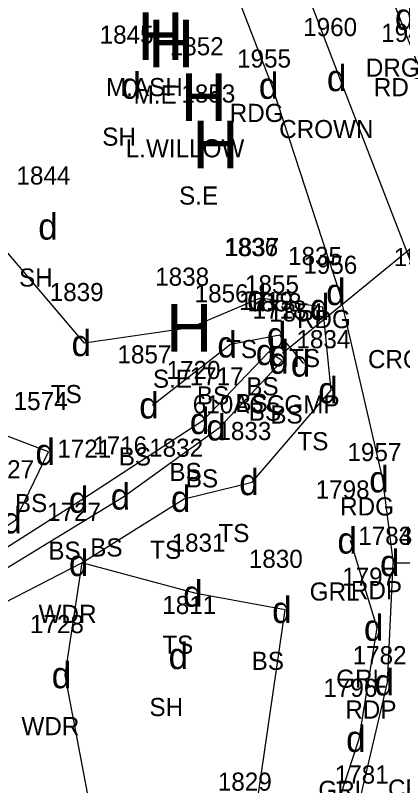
# Model space of a CAD drawing. Extents: x 461160 to 461373, y 202903 to 203086.
# Drawn here: x 461314.15 to 461330.39, y 202994.66 to 203026.97 of the extents above; entities that cross this region are included whole.
import ezdxf

# ---------------------------------------------------------------- set-up
doc = ezdxf.new("R2010")
doc.units = 0
for name, color, linetype in [('Level 11', 7, 'Continuous'), ('Level 12', 7, 'Continuous'), ('Level 14', 7, 'Continuous'), ('Level 46', 7, 'Continuous'), ('Level 47', 7, 'Continuous'), ('Level 48', 7, 'Continuous'), ('Level 49', 7, 'Continuous'), ('Level 59', 7, 'Continuous')]:
    doc.layers.add(name, color=color, linetype=linetype)

msp = doc.modelspace()

# ---------------------------------------------------------------- linework, layer by layer
at = {"layer": 'Level 11'}
for points in [[(461337.431, 203004.112), (461335.803, 203008.917), (461333.619, 203019.078), (461330.951, 203025.095), (461326.97, 203035.309), (461323.195, 203044.309), (461319.052, 203055.572), (461315.04, 203065.78), (461311.172, 203077.068)], [(461305.411, 203075.794), (461308.179, 203066.87), (461311.606, 203057.835), (461315.035, 203048.923), (461318.285, 203040.867), (461321.673, 203032.386), (461324.91, 203024.016), (461327.727, 203015.366), (461329.538, 203007.508), (461329.989, 203003.994)], [(461368.16, 202993.988), (461361.614, 202999.669), (461352.956, 203006.007), (461341.424, 203009.197), (461337.518, 203007.355), (461337.431, 203004.112), (461337.186, 202997.424), (461334.068, 202989.63), (461330.234, 202984.513), (461326.916, 202981.421), (461323.296, 202985.661), (461325.835, 202988.474), (461328.575, 202993.98), (461329.756, 202998.988), (461329.989, 203003.994), (461337.431, 203004.112), (461329.989, 203003.994)]]:
    msp.add_lwpolyline(points, dxfattribs=at)
at = {"layer": 'Level 12'}
msp.add_lwpolyline([(461323.672, 202986.332), (461326.722, 202990.981), (461328.569, 202996.619), (461329.316, 203001.28), (461328.204, 203004.939)], dxfattribs=at)
at = {"layer": 'Level 14'}
msp.add_lwpolyline([(461301.65, 202990.994), (461304.551, 202996.947), (461311.823, 203001.37), (461316.945, 203004), (461316.225, 202999.291), (461317.949, 202990.224), (461310.29, 202987.008), (461301.65, 202990.994)], dxfattribs=at)
at = {"layer": 'Level 48'}
for points in [[(461333.417, 203005.909), (461331.483, 203014.687), (461327.762, 203024.338), (461324.238, 203033.554), (461320.813, 203042.414), (461317.071, 203051.173), (461313.653, 203060.371), (461310.308, 203069.511), (461308.022, 203075.862)], [(461315.541, 203008.651), (461308.105, 203011.488), (461303.992, 203017.318), (461297.386, 203027.014), (461293.414, 203037.031), (461290.876, 203049.461), (461296.168, 203054.025)], [(461315.541, 203008.651), (461308.105, 203011.488), (461303.992, 203017.318), (461297.386, 203027.014), (461293.414, 203037.031), (461290.876, 203049.461), (461296.168, 203054.025)], [(461321.327, 202988.274), (461324.106, 202992.683), (461325.466, 203002.03), (461321.733, 203002.708), (461316.945, 203004), (461321.225, 203006.69), (461324.085, 203007.39), (461327.398, 203011.243), (461327.047, 203014.732), (461324.41, 203015.108), (461324.41, 203015.108), (461321.477, 203013.865), (461317.057, 203013.221), (461311.718, 203019.474), (461304.97, 203028.576), (461302.488, 203033.292)], [(461321.327, 202988.274), (461324.106, 202992.683), (461325.466, 203002.03), (461321.733, 203002.708), (461316.945, 203004), (461321.225, 203006.69), (461324.085, 203007.39), (461327.398, 203011.243), (461327.047, 203014.732), (461324.41, 203015.108), (461324.41, 203015.108), (461321.477, 203013.865), (461317.057, 203013.221), (461311.718, 203019.474), (461304.97, 203028.576), (461302.488, 203033.292)], [(461326.25, 203012.364), (461325.242, 203013.546), (461323.169, 203013.166), (461319.895, 203010.606)], [(461326.25, 203012.364), (461325.242, 203013.546), (461323.169, 203013.166), (461319.895, 203010.606)], [(461321.29, 202974.86), (461317.717, 202978.484), (461312.473, 202982.423), (461305.824, 202987.874), (461301.65, 202990.994), (461300.034, 202993.51), (461304.787, 202998.277), (461312.691, 203003.124), (461318.698, 203006.786), (461322.707, 203009.684), (461325.345, 203012.481), (461324.782, 203012.846), (461322.016, 203009.952), (461316.942, 203006.65), (461311.004, 203002.871), (461303.318, 202997.851), (461297.451, 202992.823)], [(461321.29, 202974.86), (461317.717, 202978.484), (461312.473, 202982.423), (461305.824, 202987.874), (461301.65, 202990.994), (461300.034, 202993.51), (461304.787, 202998.277), (461312.691, 203003.124), (461318.698, 203006.786), (461322.707, 203009.684), (461325.345, 203012.481), (461324.782, 203012.846), (461322.016, 203009.952), (461316.942, 203006.65), (461311.004, 203002.871), (461303.318, 202997.851), (461297.451, 202992.823)], [(461275.313, 203012.255), (461282.203, 203006.684), (461288.456, 203000.628), (461294.729, 202994.786), (461299.425, 202994.826), (461305.655, 203000.223), (461314.155, 203005.787), (461315.541, 203008.651)], [(461275.313, 203012.255), (461282.203, 203006.684), (461288.456, 203000.628), (461294.729, 202994.786), (461299.425, 202994.826), (461305.655, 203000.223), (461314.155, 203005.787), (461315.541, 203008.651)]]:
    msp.add_lwpolyline(points, dxfattribs=at)
at = {"layer": 'Level 59'}
msp.add_lwpolyline([(461325.352, 203012.79), (461335.427, 203021.046)], dxfattribs=at)

# ---------------------------------------------------------------- texts
at = {"layer": 'Level 14'}
for p in [(461319.271, 203025.098), (461319.717, 203024.785), (461321.087, 203022.532), (461321.574, 203020.548), (461320.477, 203012.865)]:
    msp.add_text('H', height=2, dxfattribs=at).set_placement(p)
at = {"layer": 'Level 46'}
for s, p in [(' DRG  ', (461328.564, 203024.396)), (' M.ASH  ', (461317.671, 203023.578)), (' RDG  ', (461328.899, 203023.575)), (' M.E  ', (461318.829, 203023.265)), (' RDG  ', (461322.858, 203022.496)), (' CROWN  ', (461324.932, 203021.818)), (' SH  ', (461317.511, 203021.499)), (' L.WILLOW  ', (461318.5, 203021.012)), (' S.E  ', (461320.734, 203019.028)), (' SH  ', (461314.024, 203015.59)), (' RDG  ', (461325.675, 203013.846)), (' TS  ', (461322.708, 203012.588)), (' TS  ', (461322.708, 203012.588)), (' TS  ', (461325.345, 203012.212)), (' CROWN  ', (461328.653, 203012.167)), (' S.E  ', (461319.637, 203011.345)), (' BS  ', (461323.552, 203011.026)), (' TS  ', (461315.355, 203010.701)), (' BS  ', (461321.479, 203010.646)), (' BS  ', (461323.092, 203010.326)), (' 610ACCGMP  ', (461321.307, 203010.27)), (' BS  ', (461323.655, 203009.961)), (' BS  ', (461324.56, 203009.844)), (' TS  ', (461325.696, 203008.723)), (' BS  ', (461318.205, 203008.086)), (' BS  ', (461320.326, 203007.432)), (' BS  ', (461321.017, 203007.164)), (' BS  ', (461313.851, 203006.131)), (' RDG  ', (461327.486, 203005.988)), (' TS  ', (461322.383, 203004.87)), (' BS  ', (461317.008, 203004.266)), (' BS  ', (461315.252, 203004.13)), (' TS  ', (461319.523, 203004.17)), (' GRL  ', (461326.209, 203002.419)), (' RDP  ', (461327.937, 203002.474)), (' RDP  ', (461327.937, 203002.474)), (' WDR  ', (461314.845, 203001.48)), (' TS  ', (461320.031, 203000.188)), (' BS  ', (461323.776, 202999.51)), (' GRL  ', (461327.321, 202998.76)), (' SH  ', (461319.491, 202997.573)), (' RDP  ', (461327.704, 202997.468)), (' WDR  ', (461314.125, 202996.771)), (' GRL  ', (461326.574, 202994.099)), (' CROWN  ', (461329.493, 202994.154))]:
    msp.add_text(s, height=0.76, dxfattribs=at).set_placement(p)
at = {"layer": 'Level 47'}
for p in [(461330.066, 203026.366), (461327.212, 203023.788), (461318.597, 203023.469), (461324.36, 203023.466), (461315.11, 203017.56), (461327.177, 203014.816), (461323.86, 203014.558), (461323.86, 203014.558), (461326.497, 203014.182), (461324.692, 203012.996), (461316.507, 203012.671), (461322.619, 203012.616), (461324.232, 203012.296), (461324.802, 203012.24), (461324.795, 203011.931), (461325.7, 203011.814), (461326.848, 203010.693), (461319.345, 203010.056), (461321.466, 203009.402), (461322.157, 203009.134), (461314.991, 203008.101), (461323.535, 203006.84), (461328.988, 203006.958), (461316.392, 203006.1), (461318.148, 203006.236), (461320.675, 203006.14), (461313.605, 203005.237), (461327.654, 203004.389), (461316.395, 203003.45), (461329.439, 203003.444), (461329.439, 203003.444), (461321.183, 203002.158), (461324.916, 203001.48), (461328.766, 203000.73), (461320.577, 202999.543), (461315.675, 202998.741), (461329.206, 202998.438), (461328.019, 202996.069)]:
    msp.add_text('d', height=1.1, dxfattribs=at).set_placement(p)
at = {"layer": 'Level 49'}
for s, p in [(' 1960 ', (461325.937, 203026.098)), (' 1943 ', (461329.207, 203025.855)), (' 1845 ', (461317.403, 203025.779)), (' 1852 ', (461320.343, 203025.292)), (' 1955 ', (461323.166, 203024.776)), (' 1853 ', (461320.83, 203023.308)), (' 1844 ', (461313.916, 203019.87)), (' 1836 ', (461322.627, 203016.868)), (' 1837 ', (461322.666, 203016.868)), (' 1835 ', (461325.303, 203016.492)), (' 1959 ', (461329.736, 203016.447)), (' 1956 ', (461325.944, 203016.126)), (' 1838 ', (461319.733, 203015.625)), (' 1855 ', (461323.498, 203015.306)), (' 1839 ', (461315.31, 203014.981)), (' 1856 ', (461321.386, 203014.926)), (' 1719 ', (461323.251, 203014.606)), (' 1858 ', (461323.608, 203014.55)), (' 1718 ', (461323.817, 203014.241)), (' 1854 ', (461324.506, 203014.124)), (' 1834 ', (461325.654, 203013.003)), (' 1857 ', (461318.151, 203012.366)), (' 1720 ', (461320.209, 203011.712)), (' 1717 ', (461321.179, 203011.444)), (' 1574 ', (461313.797, 203010.411)), (' 1833 ', (461322.341, 203009.15)), (' 1721 ', (461315.629, 203008.41)), (' 1716 ', (461317.131, 203008.546)), (' 1832 ', (461319.481, 203008.45)), (' 1957 ', (461327.794, 203008.268)), (' 1627 ', (461312.393, 203007.547)), (' 1798 ', (461326.46, 203006.699)), (' 1727 ', (461315.201, 203005.76)), (' 1783 ', (461328.245, 203004.754)), (' 1784 ', (461328.245, 203004.754)), (' 1831 ', (461320.42, 203004.468)), (' 1830 ', (461323.659, 203003.79)), (' 1797 ', (461327.572, 203003.04)), (' 1811 ', (461320.029, 203001.853)), (' 1728 ', (461314.481, 203001.051)), (' 1782 ', (461328.012, 202999.748)), (' 1796 ', (461326.786, 202998.379)), (' 1781 ', (461327.262, 202994.74)), (' 1829 ', (461322.359, 202994.443))]:
    msp.add_text(s, height=0.76, dxfattribs=at).set_placement(p)

doc.saveas('drawing.dxf')
